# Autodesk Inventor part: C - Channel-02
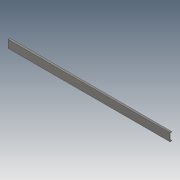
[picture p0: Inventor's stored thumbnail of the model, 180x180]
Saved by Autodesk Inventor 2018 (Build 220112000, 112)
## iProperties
Created: 2018-02
Part Number: C - Channel-02
Material: Steel, Mild
Document SubType Name: Modeling
Designer: STK
Density: 7.85 g/cm^3
Appearance: Semi-Polished
Mass: 496407 g
Surface Area: 86059.7 cm^2
Volume: 63236.6 cm^3
Author: STK
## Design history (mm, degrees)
sketch "Sketch1"
  geometry: L1 (190.5, 0)-(-190.5, 0); L2 (-177.8, -16.154)-(177.8, -16.154); L3 (-177.8, -16.154)-(-177.8, -92.075); L4 (-177.8, -92.075)-(-190.5, -92.075); L5 (-190.5, -92.075)-(-190.5, 0); L6 (177.8, -16.154)-(177.8, -92.075); L7 (177.8, -92.075)-(190.5, -92.075); L8 (190.5, -92.075)-(190.5, 0); L9 (0, 0)-(0, -92.075)
  constraints: 18 end point, 3 parallel, 2 equal length, 2 horizontal alignment, 2 vertical, 1 collinear, 1 horizontal, 1 other
  dimensions: "d0" = 381 distance of L1.start L1.end; "d1" = 12.7 distance of L6.end L7.end; "d2" = 16.1544 distance between parallel lines of L1 L2; "d3" = 92.075 distance of L4.end L1.end
extrude "Extrusion1" new body sketch "Sketch1" stored distance "d4" = 7833.2584; taper "d5" = 0 deg
sketch "Sketch2"
  geometry: L1 (0, 92.075)-(0, 16.154) reference; L2 (0, 92.075)-(158.75, 92.075); L3 (158.75, 92.075)-(158.75, 16.154); L4 (158.75, 16.154)-(0, 16.154); L5 (0, 16.154)-(0, 92.075); 1 further point
  constraints: 8 end point, 2 parallel, 1 horizontal, 1 perpendicular
  dimensions: "d6" = 158.75 distance between parallel lines of L3 L1
extrude "Extrusion2" cut sketch "Sketch2" stored distance "d7" = 25.4; taper "d8" = 0 deg
mirror "Mirror1"
sketch "Sketch3"
  geometry: L1 (0, -75.921)-(7833.258, -75.921) reference; L2 (0, 0)-(6.35, 0); L3 (6.35, 0)-(6.35, -75.921); L4 (6.35, -75.921)-(0, -75.921); L5 (0, -75.921)-(0, 0); 1 further point
  constraints: 8 end point, 2 parallel, 1 horizontal, 1 perpendicular, 1 point on line
  dimensions: "d9" = 6.35 distance between parallel lines of L5 L3
extrude "Extrusion3" cut sketch "Sketch3" stored distance "d10" = 25.4; taper "d11" = 0 deg
mirror "Mirror2"
body "Solid1"
